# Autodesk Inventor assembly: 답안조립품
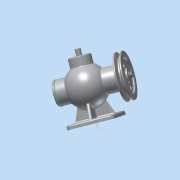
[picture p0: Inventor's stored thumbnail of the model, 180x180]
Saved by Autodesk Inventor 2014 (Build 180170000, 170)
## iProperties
Created: 2017-01
Part Number: 답안조립품
Document SubType Name: Assembly
Designer: ksu
Author: ksu
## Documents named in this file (19)
- C:\Users\ksu\Desktop\470118V1007\답안조립품.iam
- C:\Users\ksu\Desktop\470118V1007\1본체.ipt
- C:\Users\ksu\Desktop\470118V1007\470118V1007\V-벨트풀리.ipt
- C:\Users\ksu\Desktop\470118V1007\470118V1007\너트 M8.ipt
- C:\Users\ksu\Desktop\470118V1007\470118V1007\뒤커버.ipt
- C:\Users\ksu\Desktop\470118V1007\470118V1007\멈춤링- 15 x 1.ipt
- C:\Users\ksu\Desktop\470118V1007\470118V1007\멈춤링- 35x1.6.ipt
- KS B 1336 - 35x1.6.ipt
- C:\Users\ksu\Desktop\470118V1007\470118V1007\베어링- 6202.ipt
- KS B 2023 - 6202 - 15 x 35 x 11 - 7.8.ipt
- C:\Users\ksu\Desktop\470118V1007\470118V1007\볼트 M4 x 12.ipt
- C:\Users\ksu\Desktop\470118V1007\470118V1007\볼트 M4 x 16.ipt
- C:\Users\ksu\Desktop\470118V1007\470118V1007\부시.ipt
- C:\Users\ksu\Desktop\470118V1007\470118V1007\상부커버.ipt
- C:\Users\ksu\Desktop\470118V1007\470118V1007\슬라이드.ipt
- C:\Users\ksu\Desktop\470118V1007\470118V1007\앞커버.ipt
- C:\Users\ksu\Desktop\470118V1007\470118V1007\오일실 15 30 7.ipt
- C:\Users\ksu\Desktop\470118V1007\470118V1007\키 4 x 4 x 12.ipt
- C:\Users\ksu\Desktop\470118V1007\470118V1007\편심축.ipt
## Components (17 placed, 6 different names)
1. 1본체:1 — Insert:9, Insert:10, Insert:11, Mate:8, Mate:9, Insert:13, Mate:10, Mate:11, Angle:1
2. V-벨트풀리:1 — Mate:4, Mate:5, Mate:6, Insert:1
3. KS B 1336 - 35x1.6:1 — Insert:8
4. KS B 2023 - 6202 - 15 x 35 x 11 - 7.8:1 — Insert:4, Insert:5
5. KS B 2023 - 6202 - 15 x 35 x 11 - 7.8:2 — Insert:7, Insert:8
6. ISO 4762 M4 x 16:2 — Insert:14
7. ISO 4762 M4 x 16:3
8. ISO 4762 M4 x 16:4
9. ISO 4762 M4 x 16:5
10. KS B 1021 - 에 따름 ISO 1207 - 미터 A  M 4 x 12:1 — Insert:13
11. KS B 1021 - 에 따름 ISO 1207 - 미터 A  M 4 x 12:2
12. KS B 1021 - 에 따름 ISO 1207 - 미터 A  M 4 x 12:3
13. KS B 1021 - 에 따름 ISO 1207 - 미터 A  M 4 x 12:4
14. ISO 4762 M4 x 16:1 — Insert:12
15. ISO 4762 M4 x 16:6
16. ISO 4762 M4 x 16:7
17. ISO 4762 M4 x 16:8
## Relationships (19: Insert 11, Mate 7, Angle 1)
- Mate:4: V-벨트풀리:1
- Mate:5: V-벨트풀리:1
- Mate:6: V-벨트풀리:1
- Insert:1: V-벨트풀리:1
- Insert:4: KS B 2023 - 6202 - 15 x 35 x 11 - 7.8:1
- Insert:5: KS B 2023 - 6202 - 15 x 35 x 11 - 7.8:1
- Insert:7: KS B 2023 - 6202 - 15 x 35 x 11 - 7.8:2
- Insert:8: KS B 1336 - 35x1.6:1 ↔ KS B 2023 - 6202 - 15 x 35 x 11 - 7.8:2
- Insert:9: 1본체:1
- Insert:10: 1본체:1
- Insert:11: 1본체:1
- Mate:8: 1본체:1
- Insert:12: ISO 4762 M4 x 16:1
- Mate:9: 1본체:1
- Insert:13: 1본체:1 ↔ KS B 1021 - 에 따름 ISO 1207 - 미터 A  M 4 x 12:1
- Mate:10: 1본체:1
- Insert:14: ISO 4762 M4 x 16:2
- Mate:11: 1본체:1
- Angle:1: 1본체:1
